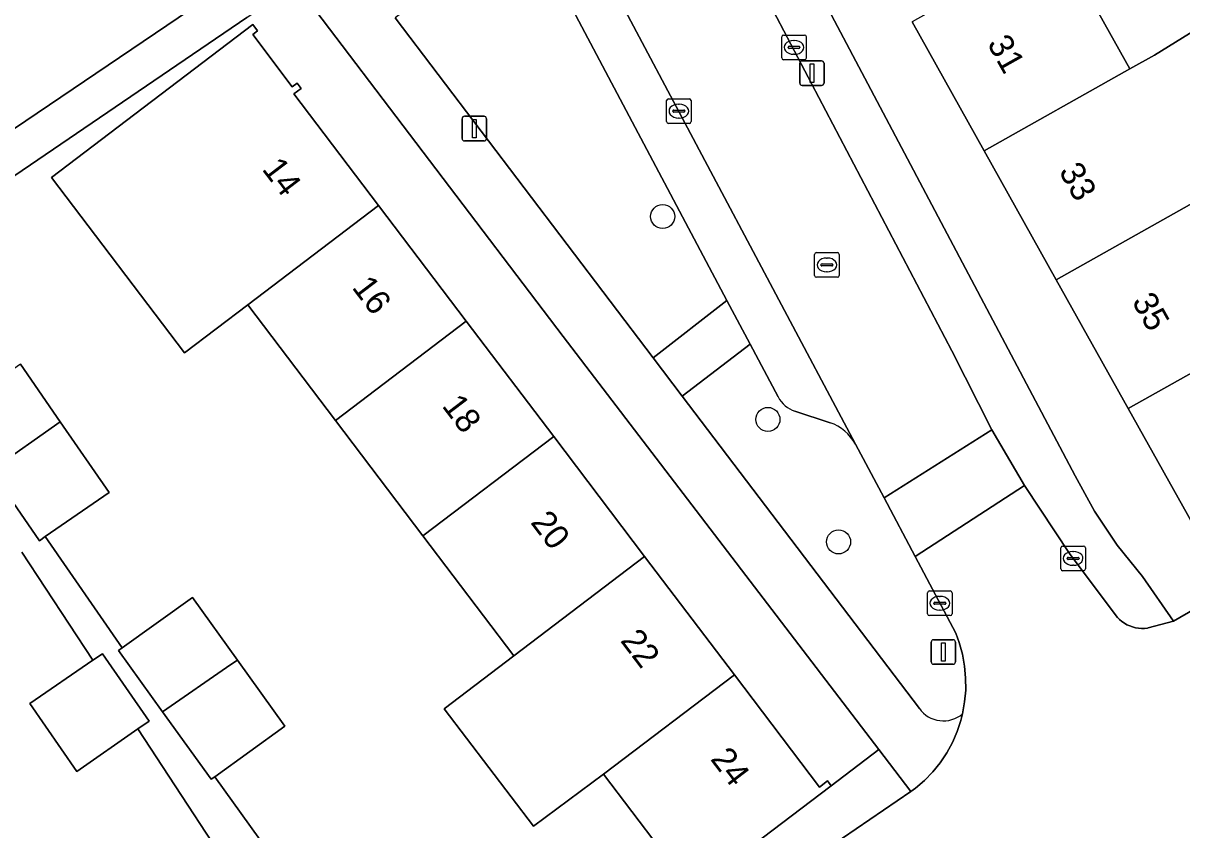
# Model space of a CAD drawing. Extents: x 157445 to 158888, y 383061 to 384688.
# Drawn here: x 158104.15 to 158151.23, y 383593.67 to 383626.43 of the extents above; entities that cross this region are included whole.
import ezdxf

# ---------------------------------------------------------------- set-up
doc = ezdxf.new("R2010")
doc.units = 0
for name, color, linetype in [('IMGEO_Boom', 7, 'Continuous'), ('IMGEO_Erf', 7, 'Continuous'), ('IMGEO_Groenvoorziening', 7, 'Continuous'), ('IMGEO_Kolk', 7, 'Continuous'), ('IMGEO_Lichtmast', 7, 'Continuous'), ('IMGEO_Pand', 7, 'Continuous'), ('IMGEO_Pand_nummerreeks', 7, 'Continuous'), ('IMGEO_Parkeervlak_open', 7, 'Continuous'), ('IMGEO_Rijbaan_lokaal_open', 7, 'Continuous'), ('IMGEO_Rioolput', 7, 'Continuous'), ('IMGEO_Voetpad_open', 7, 'Continuous')]:
    doc.layers.add(name, color=color, linetype=linetype)

msp = doc.modelspace()

# ---------------------------------------------------------------- linework, layer by layer
at = {"layer": 'IMGEO_Boom'}
for centre in [(158130.136, 383618.577), (158134.413, 383610.334), (158137.284, 383605.361)]:
    msp.add_circle(centre, 0.489, dxfattribs=at)
at = {"layer": 'IMGEO_Erf'}
for points in [[(158132.163, 383635.91), (158146.904, 383608.05), (158147.69, 383606.604), (158148.603, 383605.234), (158149.634, 383603.95), (158150.889, 383602.146), (158152.977, 383603.351), (158158.176, 383606.794), (158160.714, 383608.475), (158162.473, 383605.885), (158164.069, 383603.534), (158155.204, 383597.511), (158153.391, 383600.065), (158152.483, 383599.475), (158154.264, 383596.873), (158157.098, 383592.722), (158159.953, 383594.707), (158164.353, 383597.65), (158169.305, 383600.973), (158170.447, 383599.27), (158175.349, 383602.599), (158180.152, 383605.862)], [(158146.195, 383629.81), (158149.122, 383624.572), (158150.12, 383625.132), (158151.828, 383626.188), (158154.738, 383620.98), (158157.675, 383615.723), (158154.976, 383614.097), (158157.865, 383608.928), (158158.11, 383609.065), (158158.244, 383608.825), (158156.207, 383607.687), (158151.842, 383605.247), (158151.678, 383605.54), (158151.91, 383605.67), (158149.057, 383610.775), (158146.131, 383616.011), (158143.203, 383621.25), (158140.276, 383626.488)], [(158131.187, 383591.372), (158127.738, 383595.92), (158124.885, 383593.811), (158121.26, 383598.577), (158124.091, 383600.73), (158120.397, 383605.602), (158116.847, 383610.285), (158113.28, 383614.989), (158110.708, 383613.034), (158105.299, 383620.168), (158113.483, 383626.372), (158113.676, 383626.117), (158113.477, 383625.966), (158115.084, 383623.847), (158115.283, 383623.998), (158115.446, 383623.783), (158115.154, 383623.561), (158118.592, 383619.027), (158122.158, 383614.323), (158125.709, 383609.641), (158129.403, 383604.769), (158133.05, 383599.959), (158136.507, 383595.4), (158136.839, 383595.652), (158136.987, 383595.457), (158138.92, 383596.923), (158126.09, 383613.709), (158115.234, 383628.021)], [(158113.238, 383626.663), (158097.809, 383616.17)], [(158104.041, 383612.577), (158105.66, 383610.236), (158107.644, 383607.367), (158105.051, 383605.574), (158108.178, 383601.052), (158111.03, 383603.101), (158112.856, 383600.557), (158114.785, 383597.869), (158111.934, 383595.822), (158115.217, 383591.25), (158117.865, 383593.152), (158119.685, 383590.616), (158121.62, 383587.92), (158118.862, 383585.94), (158120.518, 383583.634), (158120.947, 383583.922), (158121.446, 383583.178), (158121.687, 383583.35), (158123.706, 383580.514), (158125.417, 383578.11), (158124.205, 383577.246), (158122.985, 383576.378)], [(158102.075, 383585.81), (158105.228, 383580.836), (158107.195, 383582.136), (158110.56, 383576.829), (158119.268, 383582.353), (158117.285, 383585.19), (158114.601, 383583.313), (158112.815, 383585.866), (158110.934, 383588.556), (158113.618, 383590.433), (158108.813, 383597.762), (158106.327, 383596.034), (158104.428, 383598.79), (158106.985, 383600.551), (158104.102, 383604.948)]]:
    msp.add_lwpolyline(points, dxfattribs=at)
at = {"layer": 'IMGEO_Groenvoorziening'}
msp.add_lwpolyline([(158106.337, 383640.104), (158094.423, 383632.103), (158102.323, 383621.168), (158114.29, 383629.267)], close=True, dxfattribs=at)
for points in [[(158126.16, 383631.546), (158126.036, 383631.782), (158119.272, 383626.654), (158129.746, 383612.838), (158132.747, 383615.167), (158126.607, 383626.742)], [(158134.826, 383611.249), (158133.689, 383613.392), (158130.933, 383611.275), (158140.569, 383598.594)], [(158136.942, 383610.202), (158135.512, 383610.672)], [(158139.131, 383607.146), (158137.97, 383609.335)], [(158142.32, 383598.376), (158142.406, 383598.857), (158142.449, 383599.343), (158142.448, 383599.832), (158142.404, 383600.318), (158142.316, 383600.798), (158142.186, 383601.269), (158142.044, 383601.656), (158140.396, 383604.762), (158139.131, 383607.146)]]:
    msp.add_lwpolyline(points, dxfattribs=at)
for centre, radius, start, end in [((158135.885, 383611.811), 1.199, 207.9775, 251.8875), ((158136.283, 383608.377), 1.94, 29.5802, 70.1322), ((158141.544, 383599.287), 1.196, 215.3836, 310.4227)]:
    msp.add_arc(centre, radius, start, end, dxfattribs=at)
at = {"layer": 'IMGEO_Kolk'}
for p, q in [((158134.973, 383625.021), (158134.973, 383625.873)), ((158135.048, 383625.947), (158135.9, 383625.947)), ((158135.974, 383625.873), (158135.974, 383625.021)), ((158135.232, 383625.441), (158135.232, 383625.453)), ((158135.67, 383625.404), (158135.272, 383625.404)), ((158135.275, 383625.49), (158135.673, 383625.49)), ((158135.461, 383625.727), (158135.486, 383625.727)), ((158135.716, 383625.453), (158135.716, 383625.441)), ((158135.9, 383624.947), (158135.048, 383624.947)), ((158135.484, 383625.167), (158135.459, 383625.167)), ((158130.294, 383622.432), (158130.294, 383623.284)), ((158130.369, 383623.358), (158131.221, 383623.358)), ((158130.782, 383623.138), (158130.807, 383623.138)), ((158131.295, 383623.284), (158131.295, 383622.432)), ((158130.553, 383622.852), (158130.553, 383622.864)), ((158130.991, 383622.815), (158130.593, 383622.815)), ((158130.596, 383622.901), (158130.994, 383622.901)), ((158130.805, 383622.578), (158130.78, 383622.578)), ((158131.037, 383622.864), (158131.037, 383622.852)), ((158131.221, 383622.358), (158130.369, 383622.358)), ((158146.314, 383604.264), (158146.314, 383605.116)), ((158146.389, 383605.19), (158147.241, 383605.19)), ((158147.315, 383605.116), (158147.315, 383604.264)), ((158146.573, 383604.684), (158146.573, 383604.696)), ((158147.011, 383604.647), (158146.613, 383604.647)), ((158146.616, 383604.733), (158147.014, 383604.733)), ((158146.802, 383604.97), (158146.827, 383604.97)), ((158147.057, 383604.696), (158147.057, 383604.684)), ((158147.241, 383604.19), (158146.389, 383604.19)), ((158146.825, 383604.41), (158146.8, 383604.41)), ((158140.898, 383602.442), (158140.898, 383603.294)), ((158140.973, 383603.368), (158141.825, 383603.368)), ((158141.899, 383603.294), (158141.899, 383602.442)), ((158141.157, 383602.862), (158141.157, 383602.874)), ((158141.595, 383602.825), (158141.197, 383602.825)), ((158141.2, 383602.911), (158141.598, 383602.911)), ((158141.386, 383603.148), (158141.411, 383603.148)), ((158141.641, 383602.874), (158141.641, 383602.862)), ((158141.825, 383602.368), (158140.973, 383602.368)), ((158141.409, 383602.588), (158141.384, 383602.588))]:
    msp.add_line(p, q, dxfattribs=at)
for points in [[(158134.973, 383625.021), (158134.973, 383625.873)], [(158135.048, 383625.947), (158135.9, 383625.947)], [(158135.974, 383625.873), (158135.974, 383625.021)], [(158135.9, 383624.947), (158135.048, 383624.947)], [(158130.294, 383622.432), (158130.294, 383623.284)], [(158130.369, 383623.358), (158131.221, 383623.358)], [(158131.295, 383623.284), (158131.295, 383622.432)], [(158131.221, 383622.358), (158130.369, 383622.358)], [(158146.314, 383604.264), (158146.314, 383605.116)], [(158146.389, 383605.19), (158147.241, 383605.19)], [(158147.315, 383605.116), (158147.315, 383604.264)], [(158147.241, 383604.19), (158146.389, 383604.19)], [(158140.898, 383602.442), (158140.898, 383603.294)], [(158140.973, 383603.368), (158141.825, 383603.368)], [(158141.899, 383603.294), (158141.899, 383602.442)], [(158141.825, 383602.368), (158140.973, 383602.368)]]:
    msp.add_lwpolyline(points, dxfattribs=at)
for centre, radius, start, end in [((158135.05, 383625.871), 0.0765, 91.552, 178.448), ((158135.05, 383625.871), 0.0765, 91.552, 178.448), ((158135.898, 383625.871), 0.0765, 1.552, 88.448), ((158135.898, 383625.871), 0.0765, 1.552, 88.448), ((158135.272, 383625.45), 0.0403, 85.8775, 175.7526), ((158135.269, 383625.44), 0.0366, 178.938, 274.7102), ((158135.673, 383625.447), 0.043, 264.8664, 352.4533), ((158135.677, 383625.452), 0.0386, 1.7309, 96.639), ((158135.05, 383625.023), 0.0765, 181.552, 268.448), ((158135.05, 383625.023), 0.0765, 181.552, 268.448), ((158135.898, 383625.023), 0.0765, 271.552, 358.448), ((158135.898, 383625.023), 0.0765, 271.552, 358.448), ((158130.371, 383623.282), 0.0765, 91.552, 178.448), ((158130.371, 383623.282), 0.0765, 91.552, 178.448), ((158131.219, 383623.282), 0.0765, 1.552, 88.448), ((158131.219, 383623.282), 0.0765, 1.552, 88.448), ((158130.593, 383622.861), 0.0403, 85.8775, 175.7526), ((158130.59, 383622.851), 0.0366, 178.938, 274.7102), ((158130.994, 383622.858), 0.043, 264.8664, 352.4533), ((158130.998, 383622.863), 0.0386, 1.7309, 96.639), ((158130.371, 383622.434), 0.0765, 181.552, 268.448), ((158130.371, 383622.434), 0.0765, 181.552, 268.448), ((158131.219, 383622.434), 0.0765, 271.552, 358.448), ((158131.219, 383622.434), 0.0765, 271.552, 358.448), ((158146.391, 383605.114), 0.0765, 91.552, 178.448), ((158146.391, 383605.114), 0.0765, 91.552, 178.448), ((158147.239, 383605.114), 0.0765, 1.552, 88.448), ((158147.239, 383605.114), 0.0765, 1.552, 88.448), ((158146.613, 383604.693), 0.0403, 85.8775, 175.7526), ((158146.61, 383604.683), 0.0366, 178.938, 274.7102), ((158147.014, 383604.69), 0.043, 264.8664, 352.4533), ((158147.018, 383604.695), 0.0386, 1.7309, 96.639), ((158146.391, 383604.266), 0.0765, 181.552, 268.448), ((158146.391, 383604.266), 0.0765, 181.552, 268.448), ((158147.239, 383604.266), 0.0765, 271.552, 358.448), ((158147.239, 383604.266), 0.0765, 271.552, 358.448), ((158140.975, 383603.292), 0.0765, 91.552, 178.448), ((158140.975, 383603.292), 0.0765, 91.552, 178.448), ((158141.823, 383603.292), 0.0765, 1.552, 88.448), ((158141.823, 383603.292), 0.0765, 1.552, 88.448), ((158141.197, 383602.871), 0.0403, 85.8775, 175.7526), ((158141.194, 383602.861), 0.0366, 178.938, 274.7102), ((158141.598, 383602.868), 0.043, 264.8664, 352.4533), ((158141.602, 383602.873), 0.0386, 1.7309, 96.639), ((158140.975, 383602.444), 0.0765, 181.552, 268.448), ((158140.975, 383602.444), 0.0765, 181.552, 268.448), ((158141.823, 383602.444), 0.0765, 271.552, 358.448), ((158141.823, 383602.444), 0.0765, 271.552, 358.448)]:
    msp.add_arc(centre, radius, start, end, dxfattribs=at)
for centre, major_axis, ratio, start_param, end_param in [((158135.46, 383625.447), (-0.387, 0.002), 0.722429, 4.712389, 7.853982), ((158135.485, 383625.447), (-0.39, 0.002), 0.717154, 1.570796, 4.712389), ((158130.781, 383622.858), (-0.387, 0.002), 0.722429, 4.712389, 7.853982), ((158130.806, 383622.858), (-0.39, 0.002), 0.717154, 1.570796, 4.712389), ((158146.801, 383604.69), (-0.387, 0.002), 0.722429, 4.712389, 7.853982), ((158146.826, 383604.69), (-0.39, 0.002), 0.717154, 1.570796, 4.712389), ((158141.385, 383602.868), (-0.387, 0.002), 0.722429, 4.712389, 7.853982), ((158141.41, 383602.868), (-0.39, 0.002), 0.717154, 1.570796, 4.712389)]:
    msp.add_ellipse(centre, major_axis=major_axis, ratio=ratio, start_param=start_param, end_param=end_param, dxfattribs=at)
at = {"layer": 'IMGEO_Lichtmast'}
for p, q in [((158135.804, 383624.9), (158136.594, 383624.9)), ((158136.594, 383624.9), (158135.804, 383624.9)), ((158135.704, 383624), (158135.704, 383624.8)), ((158135.704, 383624.8), (158135.704, 383624)), ((158136.694, 383624.8), (158136.694, 383624)), ((158136.694, 383624), (158136.694, 383624.8)), ((158136.594, 383623.9), (158135.804, 383623.9)), ((158135.804, 383623.9), (158136.594, 383623.9)), ((158121.988, 383621.749), (158121.988, 383622.549)), ((158121.988, 383622.549), (158121.988, 383621.749)), ((158122.088, 383622.649), (158122.878, 383622.649)), ((158122.878, 383622.649), (158122.088, 383622.649)), ((158122.978, 383622.549), (158122.978, 383621.749)), ((158122.978, 383621.749), (158122.978, 383622.549)), ((158122.878, 383621.649), (158122.088, 383621.649)), ((158122.088, 383621.649), (158122.878, 383621.649)), ((158141.146, 383601.387), (158141.936, 383601.387)), ((158141.936, 383601.387), (158141.146, 383601.387)), ((158141.046, 383600.487), (158141.046, 383601.287)), ((158141.046, 383601.287), (158141.046, 383600.487)), ((158142.036, 383601.287), (158142.036, 383600.487)), ((158142.036, 383600.487), (158142.036, 383601.287)), ((158141.936, 383600.387), (158141.146, 383600.387)), ((158141.146, 383600.387), (158141.936, 383600.387))]:
    msp.add_line(p, q, dxfattribs=at)
for points in [[(158136.124, 383624.775), (158136.274, 383624.775), (158136.274, 383624.025), (158136.124, 383624.025), (158136.124, 383624.775)], [(158122.408, 383622.524), (158122.558, 383622.524), (158122.558, 383621.774), (158122.408, 383621.774), (158122.408, 383622.524)], [(158141.466, 383601.262), (158141.616, 383601.262), (158141.616, 383600.512), (158141.466, 383600.512), (158141.466, 383601.262)]]:
    msp.add_lwpolyline(points, dxfattribs=at)
for centre, start, end in [((158135.804, 383624.8), 90, 180), ((158135.804, 383624.8), 90, 180), ((158136.594, 383624.8), 0, 90), ((158136.594, 383624.8), 360, 90), ((158135.804, 383624), 180, 270), ((158135.804, 383624), 180, 270), ((158136.594, 383624), 270, 0), ((158136.594, 383624), 270, 0), ((158122.088, 383622.549), 90, 180), ((158122.088, 383622.549), 90, 180), ((158122.878, 383622.549), 0, 90), ((158122.878, 383622.549), 360, 90), ((158122.088, 383621.749), 180, 270), ((158122.088, 383621.749), 180, 270), ((158122.878, 383621.749), 270, 0), ((158122.878, 383621.749), 270, 0), ((158141.146, 383601.287), 90, 180), ((158141.146, 383601.287), 90, 180), ((158141.936, 383601.287), 0, 90), ((158141.936, 383601.287), 360, 90), ((158141.146, 383600.487), 180, 270), ((158141.146, 383600.487), 180, 270), ((158141.936, 383600.487), 270, 0), ((158141.936, 383600.487), 270, 0)]:
    msp.add_arc(centre, 0.1, start, end, dxfattribs=at)
at = {"layer": 'IMGEO_Pand'}
for points in [[(158140.276, 383626.488), (158143.203, 383621.25), (158149.122, 383624.572), (158146.195, 383629.81)], [(158113.28, 383614.989), (158118.592, 383619.027), (158115.154, 383623.561), (158115.446, 383623.783), (158115.283, 383623.998), (158115.084, 383623.847), (158113.477, 383625.966), (158113.676, 383626.117), (158113.483, 383626.372), (158105.299, 383620.168), (158110.708, 383613.034)], [(158154.738, 383620.98), (158151.828, 383626.188), (158150.12, 383625.132), (158149.122, 383624.572), (158143.203, 383621.25), (158146.131, 383616.011), (158153.057, 383619.899)], [(158154.738, 383620.98), (158153.057, 383619.899), (158146.131, 383616.011), (158149.057, 383610.775), (158154.976, 383614.097), (158157.675, 383615.723)], [(158113.28, 383614.989), (158116.847, 383610.285), (158122.158, 383614.323), (158118.592, 383619.027)], [(158125.709, 383609.641), (158122.158, 383614.323), (158116.847, 383610.285), (158120.397, 383605.602)], [(158149.057, 383610.775), (158151.91, 383605.67), (158151.678, 383605.54), (158151.842, 383605.247), (158156.207, 383607.687), (158158.244, 383608.825), (158158.11, 383609.065), (158157.865, 383608.928), (158154.976, 383614.097)], [(158104.041, 383612.577), (158101.464, 383610.796), (158101.207, 383610.618), (158102.834, 383608.264), (158105.66, 383610.236)], [(158105.66, 383610.236), (158102.834, 383608.264), (158104.809, 383605.407), (158105.051, 383605.574), (158107.644, 383607.367)], [(158124.091, 383600.73), (158129.403, 383604.769), (158125.709, 383609.641), (158120.397, 383605.602)], [(158124.091, 383600.73), (158121.26, 383598.577), (158124.885, 383593.811), (158127.738, 383595.92), (158133.05, 383599.959), (158129.403, 383604.769)], [(158112.856, 383600.557), (158111.03, 383603.101), (158108.178, 383601.052), (158108.031, 383600.947), (158109.817, 383598.459), (158112.587, 383600.378)], [(158107.376, 383600.82), (158106.985, 383600.551), (158104.428, 383598.79), (158106.327, 383596.034), (158108.813, 383597.762), (158109.266, 383598.077)], [(158112.856, 383600.557), (158112.587, 383600.378), (158109.817, 383598.459), (158111.786, 383595.716), (158111.934, 383595.822), (158114.785, 383597.869)], [(158133.05, 383599.959), (158127.738, 383595.92), (158131.187, 383591.372), (158130.898, 383591.152), (158131.048, 383590.954), (158133.003, 383592.437), (158136.987, 383595.457), (158136.839, 383595.652), (158136.507, 383595.4)]]:
    msp.add_lwpolyline(points, close=True, dxfattribs=at)
at = {"layer": 'IMGEO_Parkeervlak_open'}
for points in [[(158137.97, 383609.335), (158128.266, 383627.628), (158126.16, 383631.546)], [(158125.867, 383628.12), (158126.607, 383626.742), (158132.747, 383615.167), (158133.689, 383613.392), (158134.826, 383611.249)], [(158135.512, 383610.672), (158136.942, 383610.202)]]:
    msp.add_lwpolyline(points, dxfattribs=at)
for centre, radius, start, end in [((158135.885, 383611.811), 1.199, 207.9775, 251.8875), ((158136.283, 383608.377), 1.94, 29.5802, 70.1322)]:
    msp.add_arc(centre, radius, start, end, dxfattribs=at)
at = {"layer": 'IMGEO_Rijbaan_lokaal_open'}
for points in [[(158124.77, 383634.128), (158125.088, 383633.546), (158126.036, 383631.782), (158126.16, 383631.546), (158128.266, 383627.628), (158137.97, 383609.335), (158139.131, 383607.146), (158143.516, 383609.911), (158141.888, 383613.123), (158132.215, 383631.546)], [(158152.977, 383603.351), (158150.889, 383602.146), (158149.865, 383601.867), (158149.837, 383601.862), (158149.715, 383601.849), (158149.593, 383601.847), (158149.471, 383601.856), (158149.35, 383601.875), (158149.231, 383601.905), (158149.116, 383601.946), (158149.004, 383601.997), (158148.898, 383602.058), (158148.797, 383602.128), (158148.703, 383602.206), (158148.617, 383602.293), (158146.699, 383604.842), (158144.834, 383607.654), (158140.396, 383604.762), (158142.044, 383601.656), (158142.186, 383601.269), (158142.316, 383600.798), (158142.404, 383600.318), (158142.448, 383599.832), (158142.449, 383599.343), (158142.406, 383598.857), (158142.32, 383598.376), (158142.253, 383598.112), (158142.102, 383597.656), (158141.91, 383597.215), (158141.681, 383596.792), (158141.414, 383596.392), (158141.113, 383596.018), (158140.779, 383595.672), (158140.416, 383595.357), (158140.22, 383595.223), (158136.886, 383592.947)]]:
    msp.add_lwpolyline(points, dxfattribs=at)
msp.add_lwpolyline([(158144.834, 383607.654), (158143.516, 383609.911), (158139.131, 383607.146), (158140.396, 383604.762)], close=True, dxfattribs=at)
at = {"layer": 'IMGEO_Rioolput'}
for p, q in [((158136.31, 383616.185), (158136.31, 383617.037)), ((158136.385, 383617.111), (158137.237, 383617.111)), ((158136.798, 383616.891), (158136.823, 383616.891)), ((158137.311, 383617.037), (158137.311, 383616.185)), ((158136.569, 383616.605), (158136.569, 383616.617)), ((158137.007, 383616.568), (158136.609, 383616.568)), ((158136.612, 383616.654), (158137.01, 383616.654)), ((158137.053, 383616.617), (158137.053, 383616.605)), ((158137.237, 383616.111), (158136.385, 383616.111)), ((158136.821, 383616.331), (158136.796, 383616.331))]:
    msp.add_line(p, q, dxfattribs=at)
for points in [[(158136.31, 383616.185), (158136.31, 383617.037)], [(158136.385, 383617.111), (158137.237, 383617.111)], [(158137.311, 383617.037), (158137.311, 383616.185)], [(158137.237, 383616.111), (158136.385, 383616.111)]]:
    msp.add_lwpolyline(points, dxfattribs=at)
for centre, radius, start, end in [((158136.387, 383617.035), 0.0765, 91.552, 178.448), ((158136.387, 383617.035), 0.0765, 91.552, 178.448), ((158137.235, 383617.035), 0.0765, 1.552, 88.448), ((158137.235, 383617.035), 0.0765, 1.552, 88.448), ((158136.609, 383616.614), 0.0403, 85.8775, 175.7526), ((158136.606, 383616.604), 0.0366, 178.938, 274.7102), ((158137.01, 383616.611), 0.043, 264.8664, 352.4533), ((158137.014, 383616.616), 0.0386, 1.7309, 96.639), ((158136.387, 383616.187), 0.0765, 181.552, 268.448), ((158136.387, 383616.187), 0.0765, 181.552, 268.448), ((158137.235, 383616.187), 0.0765, 271.552, 358.448), ((158137.235, 383616.187), 0.0765, 271.552, 358.448)]:
    msp.add_arc(centre, radius, start, end, dxfattribs=at)
for centre, major_axis, ratio, start_param, end_param in [((158136.797, 383616.611), (-0.387, 0.002), 0.722429, 4.712389, 7.853982), ((158136.822, 383616.611), (-0.39, 0.002), 0.717154, 1.570796, 4.712389)]:
    msp.add_ellipse(centre, major_axis=major_axis, ratio=ratio, start_param=start_param, end_param=end_param, dxfattribs=at)
at = {"layer": 'IMGEO_Voetpad_open'}
for points in [[(158132.215, 383631.546), (158141.888, 383613.123), (158143.516, 383609.911), (158144.834, 383607.654), (158146.699, 383604.842), (158148.617, 383602.293), (158148.703, 383602.206), (158148.797, 383602.128), (158148.898, 383602.058), (158149.004, 383601.997), (158149.116, 383601.946), (158149.231, 383601.905), (158149.35, 383601.875), (158149.471, 383601.856), (158149.593, 383601.847), (158149.715, 383601.849), (158149.837, 383601.862), (158149.865, 383601.867), (158150.889, 383602.146), (158149.634, 383603.95), (158148.603, 383605.234), (158147.69, 383606.604), (158146.904, 383608.05), (158132.163, 383635.91)], [(158096.755, 383615.454), (158097.809, 383616.17), (158113.238, 383626.663), (158115.234, 383628.021), (158114.29, 383629.267), (158102.323, 383621.168), (158101.116, 383620.351), (158084.006, 383608.77), (158082.103, 383607.482), (158079.022, 383605), (158078.989, 383604.985)], [(158115.234, 383628.021), (158126.09, 383613.709), (158138.92, 383596.923), (158140.22, 383595.223), (158140.416, 383595.357), (158140.779, 383595.672), (158141.113, 383596.018), (158141.414, 383596.392), (158141.681, 383596.792), (158141.91, 383597.215), (158142.102, 383597.656), (158142.253, 383598.112), (158142.32, 383598.376)], [(158140.569, 383598.594), (158130.933, 383611.275), (158129.746, 383612.838), (158119.272, 383626.654)], [(158111.175, 383575.826), (158113.625, 383577.526), (158113.956, 383577.049), (158119.152, 383580.668), (158118.737, 383581.251), (158121.446, 383583.178), (158120.947, 383583.922), (158120.518, 383583.634), (158118.862, 383585.94), (158118.621, 383585.767), (158116.651, 383588.511), (158114.866, 383590.998), (158115.217, 383591.25), (158111.934, 383595.822), (158111.786, 383595.716), (158109.817, 383598.459), (158108.031, 383600.947), (158108.178, 383601.052), (158105.051, 383605.574), (158104.809, 383605.407), (158102.834, 383608.264)], [(158104.102, 383604.948), (158106.985, 383600.551), (158107.376, 383600.82), (158109.266, 383598.077), (158108.813, 383597.762), (158113.618, 383590.433), (158115.515, 383587.722), (158117.285, 383585.19), (158119.268, 383582.353), (158110.56, 383576.829), (158108.848, 383575.743), (158106.79, 383574.438), (158102.566, 383571.761)]]:
    msp.add_lwpolyline(points, dxfattribs=at)
for points in [[(158133.689, 383613.392), (158132.747, 383615.167), (158129.746, 383612.838), (158130.933, 383611.275)], [(158140.22, 383595.223), (158138.92, 383596.923), (158136.987, 383595.457), (158133.003, 383592.437), (158131.048, 383590.954), (158127.558, 383588.307), (158128.334, 383587.166), (158130.457, 383588.609), (158131.953, 383589.622), (158136.886, 383592.947)]]:
    msp.add_lwpolyline(points, close=True, dxfattribs=at)
msp.add_arc((158141.544, 383599.287), 1.196, 215.3836, 310.4227, dxfattribs=at)

# ---------------------------------------------------------------- texts
at = {"layer": 'IMGEO_Pand_nummerreeks'}
for s, rotation, p in [('31', 299.3083, (158143.305, 383625.601)), ('14', 307.2503, (158113.825, 383620.497)), ('33', 299.3083, (158146.217, 383620.415)), ('16', 307.2503, (158117.481, 383615.69)), ('35', 299.3083, (158149.184, 383615.13)), ('18', 307.2503, (158121.138, 383610.88)), ('20', 307.2503, (158124.739, 383606.146)), ('22', 307.2503, (158128.39, 383601.343)), ('24', 307.2503, (158132.048, 383596.533))]:
    msp.add_text(s, height=1, rotation=rotation, dxfattribs=at).set_placement(p)

doc.saveas('drawing.dxf')
